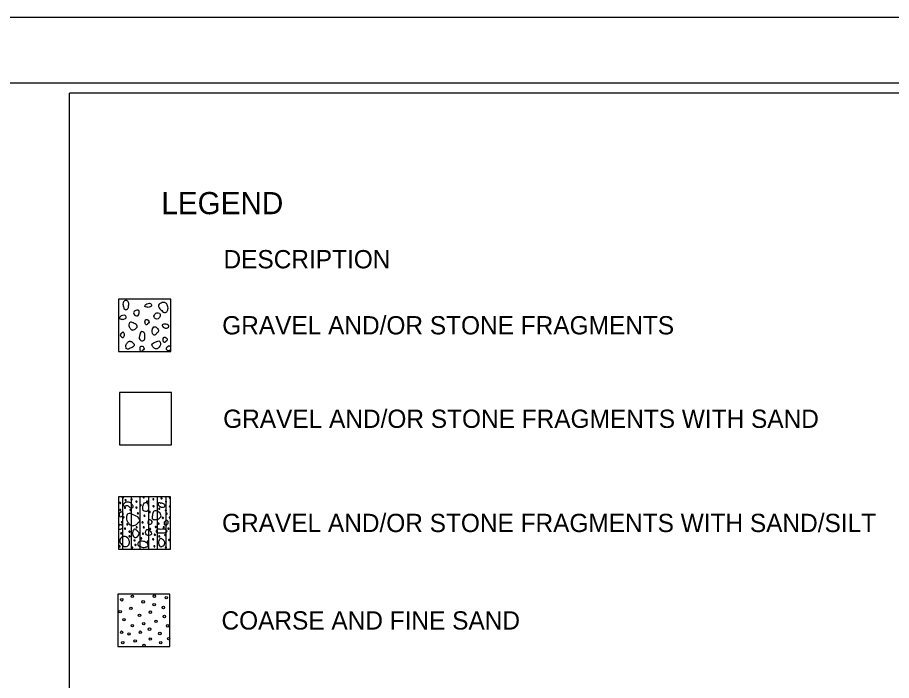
# Model space of a CAD drawing. Extents: x -5.4 to 49.9, y 13.2 to 48.4.
# Drawn here: x 14.02 to 20.72, y 43.35 to 48.43 of the extents above; entities that cross this region are included whole.
import ezdxf

# ---------------------------------------------------------------- set-up
doc = ezdxf.new("R2010")
doc.units = 0
for name, color, linetype in [('SH_Border', 7, 'Continuous'), ('SH_Cut_Line', 7, 'Continuous'), ('SH_Data', 7, 'Continuous'), ('SH_Text', 7, 'Continuous')]:
    doc.layers.add(name, color=color, linetype=linetype)

msp = doc.modelspace()

# ---------------------------------------------------------------- linework, layer by layer
at = {"layer": 'SH_Border'}
msp.add_lwpolyline([(4.2889, 47.9288), (36.2889, 47.9288), (36.2889, 26.9288), (4.2889, 26.9288)], close=True, dxfattribs=at)
at = {"layer": 'SH_Cut_Line'}
for p, q in [((14.7911, 46.2703), (14.7911, 46.2703)), ((15.1911, 46.2703), (15.1911, 46.2703)), ((14.956, 46.005), (14.9521, 45.9875)), ((14.7911, 45.8703), (14.7911, 45.8703)), ((15.1911, 45.8703), (15.1911, 45.8703)), ((14.79, 44.7555), (14.79, 44.7555)), ((14.8233, 44.3555), (14.8233, 44.7555)), ((14.8899, 44.3555), (14.8899, 44.7555)), ((14.9566, 44.3555), (14.9566, 44.7555)), ((15.0233, 44.3555), (15.0233, 44.7555)), ((15.09, 44.3555), (15.09, 44.7555)), ((15.1566, 44.3555), (15.1566, 44.7555)), ((15.19, 44.7555), (15.19, 44.7555)), ((14.79, 44.3555), (14.79, 44.3555)), ((15.19, 44.3555), (15.19, 44.3555)), ((14.7856, 44.0084), (14.7856, 44.0084)), ((15.1856, 44.0084), (15.1856, 44.0084)), ((14.7856, 43.6084), (14.7856, 43.6084)), ((15.1856, 43.6084), (15.1856, 43.6084))]:
    msp.add_line(p, q, dxfattribs=at)
msp.add_lwpolyline([(2.7889, 26.4288), (36.7889, 26.4288), (36.7889, 48.4288), (2.7889, 48.4288)], close=True, dxfattribs=at)
for centre in [(14.8163, 43.9666), (14.8972, 43.9925), (14.9802, 43.951), (15.0665, 43.9946), (15.1578, 43.9823), (14.804, 43.8759), (14.8861, 43.9016), (15.0642, 43.9286), (15.1351, 43.9076), (14.8332, 43.8145), (14.9518, 43.8468), (15.0355, 43.8714), (15.1426, 43.8386), (14.8975, 43.7685), (14.9842, 43.783), (15.029, 43.7415), (15.0787, 43.8009), (15.1679, 43.7666), (14.8152, 43.718), (14.8723, 43.7046), (14.9585, 43.718), (15.1085, 43.7082), (14.824, 43.6373), (14.9191, 43.6513), (14.987, 43.6179), (15.0346, 43.6657), (15.1146, 43.6384), (15.1754, 43.6688)]:
    msp.add_circle(centre, 0.00954, dxfattribs=at)
for points in [[(14.8308, 46.2058), (14.8251, 46.2311), (14.8297, 46.2507), (14.8458, 46.2599), (14.8653, 46.2507), (14.8688, 46.2196), (14.8607, 46.1955), (14.8458, 46.1885), (14.8332, 46.2), (14.8308, 46.2058)], [(15.0327, 46.2119), (15.0447, 46.2191), (15.0426, 46.2322), (15.0286, 46.2384), (15.0078, 46.2342), (14.9958, 46.2238), (14.9937, 46.2139), (15.0078, 46.2093), (15.0198, 46.2071), (15.0327, 46.2119)], [(15.1644, 46.2269), (15.1705, 46.1943), (15.1612, 46.174), (15.1512, 46.1673), (15.1363, 46.1707), (15.1237, 46.1829), (15.0986, 46.2129), (15.1017, 46.2316), (15.11, 46.2362), (15.1259, 46.2436), (15.1415, 46.2447), (15.1501, 46.2425), (15.1584, 46.2366), (15.1644, 46.2269)], [(14.9492, 46.1655), (14.943, 46.1447), (14.9149, 46.1499), (14.9066, 46.1666), (14.918, 46.1812), (14.9316, 46.1854), (14.9482, 46.1822), (14.9492, 46.1655)], [(15.072, 46.1574), (15.0632, 46.139), (15.0771, 46.1191), (15.0948, 46.1199), (15.111, 46.1434), (15.1051, 46.1625), (15.0852, 46.1662), (15.072, 46.1574)], [(14.8376, 46.1203), (14.8496, 46.1275), (14.8475, 46.1405), (14.8334, 46.1468), (14.8126, 46.1427), (14.8007, 46.1323), (14.7986, 46.1223), (14.8126, 46.1176), (14.8246, 46.1156), (14.8371, 46.1203)], [(15.0142, 46.0802), (15.0261, 46.0938), (15.0178, 46.1104), (15.0032, 46.1146), (14.996, 46.1053), (14.9944, 46.0901), (14.9986, 46.0786), (15.0038, 46.0745), (15.01, 46.0756), (15.0142, 46.0802)], [(14.8844, 46.042), (14.8703, 46.0655), (14.8718, 46.084), (14.8777, 46.0921), (14.8903, 46.0936), (14.9035, 46.0877), (14.9314, 46.0715), (14.9344, 46.056), (14.9292, 46.0501), (14.9189, 46.0398), (14.9072, 46.0347), (14.8998, 46.0339), (14.8918, 46.0361), (14.8844, 46.042)], [(15.0798, 46.0036), (15.0984, 46.0248), (15.0854, 46.0508), (15.0627, 46.0573), (15.0513, 46.0427), (15.0489, 46.019), (15.0554, 46.0012), (15.0636, 45.9947), (15.0732, 45.9963), (15.0798, 46.0036)], [(15.1642, 46.0749), (15.1761, 46.0675), (15.1741, 46.0545), (15.1601, 46.0482), (15.1392, 46.0525), (15.1272, 46.0629), (15.1252, 46.0727), (15.1392, 46.0775), (15.1512, 46.0795), (15.1642, 46.0749)], [(14.817, 46.0108), (14.805, 45.9977), (14.8134, 45.9811), (14.8279, 45.977), (14.8352, 45.9863), (14.8367, 46.0014), (14.8326, 46.0129), (14.8274, 46.017), (14.8212, 46.016), (14.817, 46.0113)], [(14.9521, 45.9875), (14.9502, 45.9797), (14.9549, 45.9601), (14.971, 45.9509), (14.9905, 45.9601), (14.9911, 45.9609)], [(14.9911, 45.9609), (14.9939, 45.9912), (14.9859, 46.0153), (14.971, 46.0223), (14.9583, 46.0108), (14.956, 46.005)], [(15.153, 45.9448), (15.165, 45.9583), (15.1566, 45.975), (15.1421, 45.9792), (15.1348, 45.9698), (15.1333, 45.9547), (15.1374, 45.9432), (15.1426, 45.939), (15.1488, 45.9401), (15.153, 45.9448)], [(14.8612, 45.9393), (14.8473, 45.9157), (14.8487, 45.8973), (14.8546, 45.8893), (14.8671, 45.8878), (14.8803, 45.8937), (14.9083, 45.9098), (14.9112, 45.9253), (14.9061, 45.9312), (14.8958, 45.9415), (14.884, 45.9467), (14.8766, 45.9474), (14.8686, 45.9452), (14.8612, 45.9393)], [(14.9762, 45.8763), (14.9882, 45.8898), (14.9799, 45.9065), (14.9653, 45.9107), (14.9581, 45.9013), (14.9565, 45.8862), (14.9607, 45.8747), (14.9659, 45.8705), (14.9721, 45.8717), (14.9762, 45.8763)], [(15.0984, 45.8979), (15.1125, 45.9215), (15.111, 45.9399), (15.1051, 45.948), (15.0926, 45.9495), (15.0793, 45.9436), (15.0514, 45.9274), (15.0484, 45.9119), (15.0536, 45.906), (15.0639, 45.8957), (15.0757, 45.8906), (15.083, 45.8898), (15.0911, 45.892), (15.0984, 45.8979)], [(15.1701, 45.9077), (15.1582, 45.8941), (15.1665, 45.8774), (15.1811, 45.8733), (15.1883, 45.8827), (15.1899, 45.8978), (15.1857, 45.9093), (15.1805, 45.9134), (15.1743, 45.9123), (15.1701, 45.9077)], [(14.8077, 44.7107), (14.8085, 44.7089), (14.8074, 44.7064), (14.8047, 44.7053), (14.8021, 44.7061), (14.8001, 44.7079), (14.7993, 44.7099), (14.8008, 44.7127), (14.8033, 44.7129), (14.8053, 44.7129), (14.8077, 44.7107)], [(14.8278, 44.7508), (14.8288, 44.7488), (14.8276, 44.7464), (14.8249, 44.7452), (14.8223, 44.7461), (14.8203, 44.748), (14.8195, 44.75), (14.8211, 44.7527), (14.8235, 44.753), (14.8255, 44.7528), (14.8278, 44.7508)], [(14.8267, 44.6951), (14.8437, 44.7121), (14.8777, 44.7121), (14.8956, 44.6967), (14.9029, 44.6789), (14.8947, 44.6708), (14.8777, 44.6749), (14.8648, 44.6854), (14.8535, 44.6886), (14.8348, 44.6845), (14.8284, 44.6886), (14.8267, 44.6951)], [(14.8493, 44.7313), (14.8501, 44.7293), (14.849, 44.7269), (14.8463, 44.7258), (14.8437, 44.7267), (14.8417, 44.7285), (14.8409, 44.7305), (14.8425, 44.7333), (14.8449, 44.7335), (14.8469, 44.7333), (14.8493, 44.7313)], [(14.895, 44.7379), (14.896, 44.7359), (14.8948, 44.7334), (14.8921, 44.7323), (14.8895, 44.7331), (14.8875, 44.735), (14.8867, 44.737), (14.8883, 44.7397), (14.8907, 44.74), (14.8927, 44.7399), (14.895, 44.7379)], [(14.9328, 44.7208), (14.9337, 44.7189), (14.9325, 44.7165), (14.9298, 44.7153), (14.9272, 44.7162), (14.9252, 44.7181), (14.9243, 44.7201), (14.9259, 44.7228), (14.9283, 44.7231), (14.9303, 44.7229), (14.9328, 44.7208)], [(14.9648, 44.6929), (14.9656, 44.691), (14.9645, 44.6885), (14.9618, 44.6874), (14.9592, 44.6883), (14.9572, 44.6901), (14.9563, 44.6921), (14.9579, 44.6949), (14.9604, 44.6951), (14.9624, 44.695), (14.9648, 44.6929)], [(14.9824, 44.6959), (14.9766, 44.6707), (14.9812, 44.6512), (14.9972, 44.642), (15.0167, 44.6512), (15.0201, 44.6821), (15.0121, 44.7062), (14.9972, 44.7131), (14.9846, 44.7016), (14.9824, 44.6959)], [(14.988, 44.753), (14.9889, 44.751), (14.9877, 44.7486), (14.985, 44.7475), (14.9825, 44.7484), (14.9805, 44.7502), (14.9796, 44.7522), (14.9811, 44.755), (14.9836, 44.7552), (14.9856, 44.7551), (14.988, 44.753)], [(15.015, 44.7204), (15.0159, 44.7185), (15.0147, 44.7161), (15.012, 44.7149), (15.0094, 44.7159), (15.0074, 44.7177), (15.0066, 44.7197), (15.0081, 44.7224), (15.0106, 44.7227), (15.0126, 44.7225), (15.015, 44.7204)], [(15.062, 44.739), (15.0628, 44.7371), (15.0617, 44.7347), (15.059, 44.7335), (15.0564, 44.7344), (15.0544, 44.7362), (15.0536, 44.7382), (15.0551, 44.741), (15.0576, 44.7412), (15.0596, 44.7411), (15.062, 44.739)], [(15.0986, 44.7092), (15.0992, 44.6897), (15.1095, 44.6783), (15.1266, 44.6725), (15.1404, 44.6754), (15.1461, 44.6891), (15.1381, 44.7018), (15.1266, 44.7074), (15.1198, 44.7092), (15.1135, 44.7069), (15.1084, 44.712), (15.1021, 44.7126), (15.0986, 44.7092)], [(15.1248, 44.7452), (15.1256, 44.7434), (15.1245, 44.741), (15.1218, 44.7398), (15.1192, 44.7406), (15.1172, 44.7426), (15.1163, 44.7446), (15.1179, 44.7472), (15.1203, 44.7476), (15.1223, 44.7474), (15.1248, 44.7452)], [(15.1591, 44.7204), (15.16, 44.7185), (15.1589, 44.7161), (15.1561, 44.7149), (15.1536, 44.7159), (15.1516, 44.7177), (15.1507, 44.7197), (15.1523, 44.7224), (15.1547, 44.7227), (15.1567, 44.7225), (15.1591, 44.7204)], [(15.1881, 44.7509), (15.189, 44.7491), (15.1879, 44.7467), (15.1851, 44.7455), (15.1825, 44.7463), (15.1805, 44.7482), (15.1797, 44.7502), (15.1813, 44.7529), (15.1837, 44.7532), (15.1857, 44.7531), (15.1881, 44.7509)], [(14.8055, 44.6362), (14.8135, 44.6402), (14.8232, 44.6356), (14.8278, 44.6247), (14.8244, 44.6144), (14.817, 44.6064), (14.8089, 44.6029), (14.7981, 44.6093), (14.7969, 44.6189), (14.7975, 44.627), (14.8055, 44.6362)], [(14.8093, 44.6556), (14.8101, 44.6537), (14.8091, 44.6513), (14.8063, 44.6501), (14.8037, 44.651), (14.8017, 44.6529), (14.8009, 44.6549), (14.8025, 44.6576), (14.8049, 44.6579), (14.8069, 44.6577), (14.8093, 44.6556)], [(14.8448, 44.6735), (14.8458, 44.6715), (14.8446, 44.6691), (14.842, 44.6679), (14.8394, 44.6689), (14.8374, 44.6707), (14.8365, 44.6727), (14.8381, 44.6754), (14.8405, 44.6757), (14.8426, 44.6755), (14.8448, 44.6735)], [(14.8741, 44.547), (14.8523, 44.5837), (14.8546, 44.6124), (14.8638, 44.625), (14.8832, 44.6273), (14.9039, 44.6181), (14.9474, 44.5929), (14.952, 44.5689), (14.944, 44.5597), (14.9279, 44.5436), (14.9096, 44.5356), (14.8981, 44.5344), (14.8856, 44.5379), (14.8741, 44.547)], [(14.8871, 44.6556), (14.8879, 44.6537), (14.8868, 44.6513), (14.8841, 44.6501), (14.8815, 44.651), (14.8795, 44.6529), (14.8786, 44.6549), (14.8802, 44.6576), (14.8826, 44.6579), (14.8846, 44.6577), (14.8871, 44.6556)], [(14.9327, 44.6745), (14.9336, 44.6727), (14.9324, 44.6702), (14.9297, 44.6691), (14.9271, 44.67), (14.9251, 44.6718), (14.9242, 44.6738), (14.9258, 44.6765), (14.9282, 44.6768), (14.9303, 44.6767), (14.9327, 44.6745)], [(14.9439, 44.6299), (14.9448, 44.628), (14.9436, 44.6256), (14.9409, 44.6244), (14.9383, 44.6253), (14.9363, 44.6272), (14.9355, 44.6292), (14.9371, 44.6319), (14.9395, 44.6322), (14.9415, 44.632), (14.9439, 44.6299)], [(15.0345, 44.641), (15.0353, 44.6391), (15.0341, 44.6367), (15.0314, 44.6355), (15.0289, 44.6364), (15.0268, 44.6383), (15.026, 44.6403), (15.0276, 44.643), (15.03, 44.6433), (15.032, 44.6431), (15.0345, 44.641)], [(15.0507, 44.6116), (15.0604, 44.644), (15.1041, 44.6359), (15.1171, 44.61), (15.0993, 44.5873), (15.0782, 44.5809), (15.0523, 44.5857), (15.0507, 44.6116)], [(15.0636, 44.6848), (15.0645, 44.6829), (15.0633, 44.6804), (15.0606, 44.6794), (15.058, 44.6802), (15.056, 44.682), (15.0551, 44.684), (15.0567, 44.6868), (15.0591, 44.687), (15.0611, 44.6869), (15.0636, 44.6848)], [(15.1073, 44.6653), (15.1081, 44.6634), (15.1071, 44.661), (15.1043, 44.6599), (15.1017, 44.6607), (15.0997, 44.6626), (15.0989, 44.6646), (15.1005, 44.6673), (15.1029, 44.6676), (15.1049, 44.6674), (15.1073, 44.6653)], [(15.1576, 44.6524), (15.1584, 44.6504), (15.1572, 44.648), (15.1545, 44.6469), (15.152, 44.6478), (15.1499, 44.6496), (15.1491, 44.6516), (15.1506, 44.6544), (15.1531, 44.6546), (15.1551, 44.6545), (15.1576, 44.6524)], [(15.164, 44.628), (15.1649, 44.6262), (15.1637, 44.6238), (15.161, 44.6226), (15.1584, 44.6234), (15.1564, 44.6253), (15.1556, 44.6273), (15.1571, 44.63), (15.1596, 44.6304), (15.1616, 44.6302), (15.164, 44.628)], [(15.1889, 44.6824), (15.1897, 44.6806), (15.1886, 44.6781), (15.1859, 44.677), (15.1833, 44.6778), (15.1813, 44.6797), (15.1804, 44.6817), (15.182, 44.6844), (15.1844, 44.6847), (15.1865, 44.6846), (15.1889, 44.6824)], [(14.8212, 44.5619), (14.8221, 44.5599), (14.821, 44.5575), (14.8182, 44.5564), (14.8156, 44.5573), (14.8136, 44.5591), (14.8128, 44.5611), (14.8144, 44.5639), (14.8168, 44.5641), (14.8188, 44.564), (14.8212, 44.5619)], [(14.8336, 44.6009), (14.8345, 44.5991), (14.8333, 44.5966), (14.8306, 44.5955), (14.8281, 44.5964), (14.8261, 44.5982), (14.8251, 44.6002), (14.8267, 44.6029), (14.8292, 44.6032), (14.8312, 44.6031), (14.8336, 44.6009)], [(14.9794, 44.5609), (14.9802, 44.559), (14.9791, 44.5566), (14.9764, 44.5554), (14.9738, 44.5563), (14.9718, 44.5582), (14.9709, 44.5602), (14.9725, 44.5629), (14.975, 44.5632), (14.977, 44.563), (14.9794, 44.5609)], [(14.9935, 44.6118), (14.9945, 44.6098), (14.9934, 44.6074), (14.9906, 44.6062), (14.9881, 44.607), (14.9861, 44.6089), (14.9852, 44.6109), (14.9868, 44.6136), (14.9892, 44.6139), (14.9912, 44.6138), (14.9935, 44.6118)], [(15.0171, 44.5614), (15.0219, 44.5776), (15.0437, 44.5735), (15.0502, 44.5605), (15.0413, 44.5492), (15.0308, 44.5459), (15.0178, 44.5484), (15.0171, 44.5614)], [(15.1349, 44.5956), (15.1357, 44.5938), (15.1346, 44.5914), (15.1318, 44.5902), (15.1292, 44.591), (15.1272, 44.5929), (15.1264, 44.5949), (15.128, 44.5976), (15.1304, 44.5979), (15.1324, 44.5978), (15.1349, 44.5956)], [(15.1503, 44.5721), (15.1578, 44.5755), (15.1675, 44.5709), (15.1721, 44.56), (15.1686, 44.5497), (15.1612, 44.5417), (15.1532, 44.5383), (15.1423, 44.5446), (15.1411, 44.5543), (15.1417, 44.5624), (15.1503, 44.5721)], [(15.1875, 44.5979), (15.1884, 44.5961), (15.1872, 44.5937), (15.1845, 44.5925), (15.1819, 44.5933), (15.1799, 44.5952), (15.1791, 44.5972), (15.1806, 44.5999), (15.1831, 44.6002), (15.1851, 44.6001), (15.1875, 44.5979)], [(14.7924, 44.5258), (14.7964, 44.5404), (14.8183, 44.5364), (14.8247, 44.5234), (14.8158, 44.512), (14.8053, 44.5088), (14.7924, 44.5112), (14.7924, 44.5258)], [(14.8448, 44.5131), (14.8458, 44.5111), (14.8446, 44.5087), (14.842, 44.5075), (14.8394, 44.5084), (14.8374, 44.5103), (14.8365, 44.5123), (14.8381, 44.5149), (14.8405, 44.5153), (14.8426, 44.5151), (14.8448, 44.5131)], [(14.8623, 44.5458), (14.8633, 44.5438), (14.8621, 44.5414), (14.8595, 44.5402), (14.8569, 44.541), (14.8549, 44.5429), (14.8541, 44.5449), (14.8556, 44.5476), (14.8581, 44.5479), (14.8601, 44.5478), (14.8623, 44.5458)], [(14.8791, 44.4901), (14.8801, 44.4881), (14.879, 44.4857), (14.8762, 44.4845), (14.8736, 44.4854), (14.8716, 44.4873), (14.8708, 44.4893), (14.8724, 44.492), (14.8748, 44.4923), (14.8768, 44.4921), (14.8791, 44.4901)], [(14.9299, 44.4976), (14.9486, 44.4774), (14.9356, 44.4514), (14.9129, 44.4449), (14.9016, 44.4595), (14.8991, 44.483), (14.9056, 44.5009), (14.9137, 44.5074), (14.9235, 44.5057), (14.9299, 44.4976)], [(14.9341, 44.5243), (14.9349, 44.5224), (14.9337, 44.52), (14.9311, 44.5189), (14.9285, 44.5197), (14.9265, 44.5216), (14.9256, 44.5236), (14.9271, 44.5263), (14.9296, 44.5266), (14.9316, 44.5264), (14.9341, 44.5243)], [(14.9884, 44.5233), (14.9892, 44.5214), (14.9881, 44.519), (14.9854, 44.5179), (14.9828, 44.5187), (14.9808, 44.5206), (14.9799, 44.5226), (14.9815, 44.5253), (14.9839, 44.5256), (14.9859, 44.5254), (14.9884, 44.5233)], [(15.0073, 44.5054), (14.9984, 44.4795), (15.0049, 44.4641), (15.0154, 44.4584), (15.0341, 44.4609), (15.0437, 44.4698), (15.0421, 44.4828), (15.03, 44.4965), (15.0195, 44.5022), (15.0138, 44.5063), (15.0073, 44.5054)], [(15.0376, 44.5097), (15.0386, 44.5079), (15.0374, 44.5054), (15.0346, 44.5043), (15.0321, 44.5051), (15.0301, 44.507), (15.0292, 44.509), (15.0308, 44.5117), (15.0332, 44.512), (15.0352, 44.5119), (15.0376, 44.5097)], [(15.0814, 44.5259), (15.0822, 44.524), (15.0811, 44.5216), (15.0784, 44.5204), (15.0758, 44.5214), (15.0738, 44.5232), (15.073, 44.5252), (15.0746, 44.5279), (15.077, 44.5282), (15.079, 44.528), (15.0814, 44.5259)], [(15.116, 44.5054), (15.1549, 44.503), (15.163, 44.4893), (15.1492, 44.4813), (15.1206, 44.4789), (15.0942, 44.4801), (15.0794, 44.4881), (15.0816, 44.5008), (15.116, 44.5054)], [(15.1025, 44.5519), (15.1033, 44.55), (15.1021, 44.5475), (15.0995, 44.5464), (15.0969, 44.5473), (15.0949, 44.5491), (15.094, 44.5511), (15.0956, 44.5539), (15.0981, 44.5541), (15.1001, 44.554), (15.1025, 44.5519)], [(15.1416, 44.5244), (15.1427, 44.5224), (15.1416, 44.52), (15.1388, 44.5189), (15.1362, 44.5197), (15.1342, 44.5216), (15.1334, 44.5236), (15.135, 44.5263), (15.1374, 44.5266), (15.1394, 44.5264), (15.1416, 44.5244)], [(15.1775, 44.5129), (15.1783, 44.5111), (15.1771, 44.5087), (15.1745, 44.5075), (15.1719, 44.5084), (15.1699, 44.5103), (15.169, 44.5123), (15.1705, 44.5149), (15.173, 44.5153), (15.175, 44.5151), (15.1775, 44.5129)], [(14.8146, 44.3897), (14.8008, 44.4184), (14.8226, 44.4493), (14.8501, 44.4481), (14.8752, 44.4114), (14.8661, 44.3817), (14.8351, 44.3759), (14.8146, 44.3897)], [(14.8156, 44.4774), (14.8166, 44.4754), (14.8155, 44.473), (14.8128, 44.4719), (14.8102, 44.4727), (14.8082, 44.4746), (14.8074, 44.4766), (14.8089, 44.4793), (14.8114, 44.4796), (14.8134, 44.4794), (14.8156, 44.4774)], [(14.8788, 44.4544), (14.8798, 44.4524), (14.8786, 44.4499), (14.876, 44.4488), (14.8734, 44.4496), (14.8714, 44.4514), (14.8705, 44.4534), (14.8721, 44.4562), (14.8746, 44.4564), (14.8766, 44.4564), (14.8788, 44.4544)], [(14.9177, 44.4224), (14.9187, 44.4204), (14.9176, 44.4179), (14.9148, 44.4168), (14.9122, 44.4176), (14.9102, 44.4194), (14.9094, 44.4214), (14.911, 44.4242), (14.9134, 44.4244), (14.9154, 44.4244), (14.9177, 44.4224)], [(14.9696, 44.4384), (14.9705, 44.4365), (14.9694, 44.4341), (14.9666, 44.4329), (14.9641, 44.4339), (14.9621, 44.4357), (14.9612, 44.4377), (14.9628, 44.4404), (14.9652, 44.4407), (14.9672, 44.4405), (14.9696, 44.4384)], [(14.9826, 44.474), (14.9835, 44.4722), (14.9823, 44.4698), (14.9796, 44.4686), (14.9771, 44.4694), (14.9751, 44.4714), (14.9741, 44.4734), (14.9757, 44.476), (14.9781, 44.4764), (14.9801, 44.4762), (14.9826, 44.474)], [(15.0604, 44.4319), (15.0612, 44.43), (15.0601, 44.4276), (15.0573, 44.4264), (15.0547, 44.4274), (15.0527, 44.4292), (15.0519, 44.4312), (15.0535, 44.4339), (15.0559, 44.4342), (15.0579, 44.434), (15.0604, 44.4319)], [(15.0733, 44.4659), (15.0741, 44.4641), (15.0731, 44.4617), (15.0703, 44.4605), (15.0677, 44.4614), (15.0657, 44.4632), (15.0649, 44.4653), (15.0665, 44.4679), (15.0689, 44.4683), (15.0709, 44.4681), (15.0733, 44.4659)], [(15.1287, 44.4273), (15.1473, 44.4063), (15.1344, 44.3803), (15.1117, 44.3739), (15.1004, 44.3884), (15.098, 44.4119), (15.1044, 44.4298), (15.1126, 44.4362), (15.1222, 44.4346), (15.1287, 44.4273)], [(15.1073, 44.4533), (15.1081, 44.4514), (15.1069, 44.449), (15.1043, 44.4478), (15.1017, 44.4487), (15.0997, 44.4505), (15.0988, 44.4525), (15.1004, 44.4553), (15.1028, 44.4556), (15.1048, 44.4554), (15.1073, 44.4533)], [(15.1531, 44.4644), (15.154, 44.4624), (15.1529, 44.46), (15.1501, 44.4589), (15.1475, 44.4598), (15.1455, 44.4616), (15.1447, 44.4636), (15.1463, 44.4664), (15.1487, 44.4666), (15.1507, 44.4664), (15.1531, 44.4644)], [(15.1832, 44.4262), (15.184, 44.4243), (15.1829, 44.4219), (15.1802, 44.4207), (15.1776, 44.4216), (15.1756, 44.4234), (15.1747, 44.4254), (15.1763, 44.4282), (15.1787, 44.4284), (15.1807, 44.4283), (15.1832, 44.4262)], [(14.8045, 44.3768), (14.8053, 44.3749), (14.8041, 44.3725), (14.8015, 44.3714), (14.7989, 44.3722), (14.7969, 44.3741), (14.796, 44.3761), (14.7976, 44.3788), (14.8001, 44.3791), (14.8021, 44.3789), (14.8045, 44.3768)], [(14.9, 44.3687), (14.9009, 44.3669), (14.8997, 44.3644), (14.897, 44.3633), (14.8944, 44.3642), (14.8924, 44.366), (14.8916, 44.368), (14.8931, 44.3708), (14.8956, 44.371), (14.8976, 44.3709), (14.9, 44.3687)], [(14.925, 44.3891), (14.926, 44.3871), (14.9248, 44.3847), (14.9221, 44.3835), (14.9196, 44.3844), (14.9176, 44.3863), (14.9166, 44.3883), (14.9182, 44.3909), (14.9207, 44.3913), (14.9227, 44.3911), (14.925, 44.3891)], [(14.9596, 44.3742), (14.9401, 44.3855), (14.9433, 44.4058), (14.9652, 44.4155), (14.9976, 44.409), (15.0162, 44.3928), (15.0195, 44.3774), (14.9976, 44.3701), (14.979, 44.3669), (14.9596, 44.3742)], [(15.0181, 44.4142), (15.0191, 44.4122), (15.018, 44.4098), (15.0152, 44.4086), (15.0126, 44.4095), (15.0106, 44.4114), (15.0098, 44.4134), (15.0114, 44.4161), (15.0138, 44.4164), (15.0158, 44.4162), (15.0181, 44.4142)], [(15.0701, 44.3784), (15.0709, 44.3765), (15.0698, 44.3741), (15.0671, 44.373), (15.0645, 44.3739), (15.0625, 44.3757), (15.0616, 44.3777), (15.0632, 44.3804), (15.0656, 44.3807), (15.0676, 44.3806), (15.0701, 44.3784)], [(15.1582, 44.3697), (15.1592, 44.3676), (15.1581, 44.3652), (15.1553, 44.3641), (15.1528, 44.3649), (15.1507, 44.3668), (15.1499, 44.3688), (15.1515, 44.3715), (15.1539, 44.3718), (15.1559, 44.3717), (15.1582, 44.3697)]]:
    msp.add_spline(points, degree=3, dxfattribs=at)
at = {"layer": 'SH_Data'}
for p in [(14.4153, 29.9123), (24.59, 47.8483)]:
    msp.add_line(p, (14.4153, 47.8483), dxfattribs=at)
for points in [[(14.7911, 45.8703), (15.1911, 45.8703), (15.1911, 46.2703), (14.7911, 46.2703)], [(14.7984, 45.1538), (15.1984, 45.1538), (15.1984, 45.5538), (14.7984, 45.5538)], [(14.79, 44.3555), (15.19, 44.3555), (15.19, 44.7555), (14.79, 44.7555)], [(14.7856, 43.6084), (15.1856, 43.6084), (15.1856, 44.0084), (14.7856, 44.0084)]]:
    msp.add_lwpolyline(points, close=True, dxfattribs=at)

# ---------------------------------------------------------------- texts
at = {"layer": 'SH_Text'}
for s, height, p in [('LEGEND', 0.17, (15.1197, 46.9213)), ('DESCRIPTION', 0.14, (15.5961, 46.5065)), ('GRAVEL AND/OR STONE FRAGMENTS                 ', 0.14, (15.5861, 46.0002)), ('GRAVEL AND/OR STONE FRAGMENTS WITH SAND       ', 0.14, (15.5934, 45.2838)), ('GRAVEL AND/OR STONE FRAGMENTS WITH SAND/SILT       ', 0.14, (15.5849, 44.4855)), ('COARSE AND FINE SAND                         ', 0.14, (15.5805, 43.7384))]:
    msp.add_text(s, height=height, dxfattribs=at).set_placement(p)

doc.saveas('drawing.dxf')
